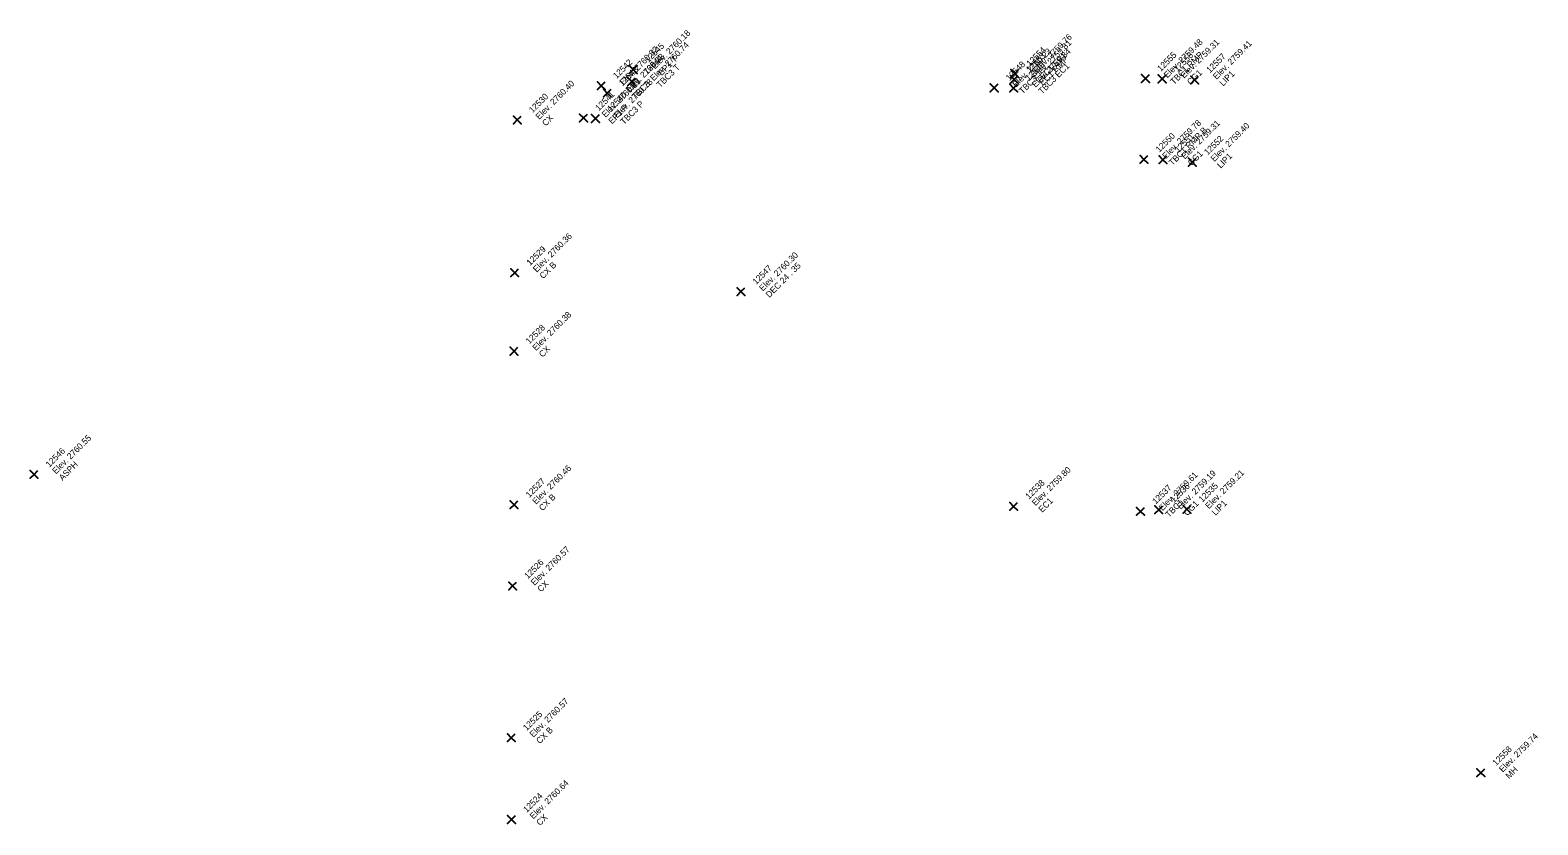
# Model space of a CAD drawing. Extents: x 2493999 to 2503109, y 700767 to 706646.
# Drawn here: x 2502207.3 to 2502265.7, y 702426.3 to 702457 of the extents above; entities that cross this region are included whole.
import ezdxf

# ---------------------------------------------------------------- set-up
doc = ezdxf.new("R2010")
doc.units = 0
doc.layers.add('ALG_CL_BLUE_Horiz', color=7, linetype='Continuous')
doc.layers.add('DES_SURFACE_Existing-Ground', color=7, linetype='Continuous')

msp = doc.modelspace()

# ---------------------------------------------------------------- linework, layer by layer
at = {"layer": 'ALG_CL_BLUE_Horiz'}
for points in [[(2502230.665, 702455.483), (2502230.515, 702455.633), (2502230.665, 702455.483), (2502230.515, 702455.333), (2502230.665, 702455.483), (2502230.815, 702455.333), (2502230.665, 702455.483), (2502230.815, 702455.633)], [(2502229.432, 702454.854), (2502229.282, 702455.004), (2502229.432, 702454.854), (2502229.282, 702454.704), (2502229.432, 702454.854), (2502229.582, 702454.704), (2502229.432, 702454.854), (2502229.582, 702455.004)], [(2502230.61, 702455.016), (2502230.46, 702455.166), (2502230.61, 702455.016), (2502230.46, 702454.866), (2502230.61, 702455.016), (2502230.76, 702454.866), (2502230.61, 702455.016), (2502230.76, 702455.166)], [(2502245.416, 702455.103), (2502245.266, 702455.253), (2502245.416, 702455.103), (2502245.266, 702454.953), (2502245.416, 702455.103), (2502245.566, 702454.953), (2502245.416, 702455.103), (2502245.566, 702455.253)], [(2502245.43, 702455.328), (2502245.28, 702455.478), (2502245.43, 702455.328), (2502245.28, 702455.178), (2502245.43, 702455.328), (2502245.58, 702455.178), (2502245.43, 702455.328), (2502245.58, 702455.478)], [(2502250.493, 702455.137), (2502250.343, 702455.287), (2502250.493, 702455.137), (2502250.343, 702454.987), (2502250.493, 702455.137), (2502250.643, 702454.987), (2502250.493, 702455.137), (2502250.643, 702455.287)], [(2502251.139, 702455.124), (2502250.989, 702455.274), (2502251.139, 702455.124), (2502250.989, 702454.974), (2502251.139, 702455.124), (2502251.289, 702454.974), (2502251.139, 702455.124), (2502251.289, 702455.274)], [(2502252.393, 702455.078), (2502252.243, 702455.228), (2502252.393, 702455.078), (2502252.243, 702454.928), (2502252.393, 702455.078), (2502252.543, 702454.928), (2502252.393, 702455.078), (2502252.543, 702455.228)], [(2502229.662, 702454.571), (2502229.512, 702454.721), (2502229.662, 702454.571), (2502229.512, 702454.421), (2502229.662, 702454.571), (2502229.812, 702454.421), (2502229.662, 702454.571), (2502229.812, 702454.721)], [(2502244.636, 702454.775), (2502244.486, 702454.925), (2502244.636, 702454.775), (2502244.486, 702454.625), (2502244.636, 702454.775), (2502244.786, 702454.625), (2502244.636, 702454.775), (2502244.786, 702454.925)], [(2502245.387, 702454.766), (2502245.237, 702454.916), (2502245.387, 702454.766), (2502245.237, 702454.616), (2502245.387, 702454.766), (2502245.537, 702454.616), (2502245.387, 702454.766), (2502245.537, 702454.916)], [(2502226.178, 702453.53), (2502226.028, 702453.68), (2502226.178, 702453.53), (2502226.028, 702453.38), (2502226.178, 702453.53), (2502226.328, 702453.38), (2502226.178, 702453.53), (2502226.328, 702453.68)], [(2502228.744, 702453.609), (2502228.594, 702453.759), (2502228.744, 702453.609), (2502228.594, 702453.459), (2502228.744, 702453.609), (2502228.894, 702453.459), (2502228.744, 702453.609), (2502228.894, 702453.759)], [(2502229.207, 702453.588), (2502229.057, 702453.738), (2502229.207, 702453.588), (2502229.057, 702453.438), (2502229.207, 702453.588), (2502229.357, 702453.438), (2502229.207, 702453.588), (2502229.357, 702453.738)], [(2502250.434, 702452.005), (2502250.284, 702452.155), (2502250.434, 702452.005), (2502250.284, 702451.855), (2502250.434, 702452.005), (2502250.584, 702451.855), (2502250.434, 702452.005), (2502250.584, 702452.155)], [(2502251.166, 702451.992), (2502251.016, 702452.142), (2502251.166, 702451.992), (2502251.016, 702451.842), (2502251.166, 702451.992), (2502251.316, 702451.842), (2502251.166, 702451.992), (2502251.316, 702452.142)], [(2502252.305, 702451.897), (2502252.155, 702452.047), (2502252.305, 702451.897), (2502252.155, 702451.747), (2502252.305, 702451.897), (2502252.455, 702451.747), (2502252.305, 702451.897), (2502252.455, 702452.047)], [(2502226.082, 702447.623), (2502225.932, 702447.773), (2502226.082, 702447.623), (2502225.932, 702447.473), (2502226.082, 702447.623), (2502226.232, 702447.473), (2502226.082, 702447.623), (2502226.232, 702447.773)], [(2502234.834, 702446.889), (2502234.684, 702447.039), (2502234.834, 702446.889), (2502234.684, 702446.739), (2502234.834, 702446.889), (2502234.984, 702446.739), (2502234.834, 702446.889), (2502234.984, 702447.039)], [(2502226.056, 702444.587), (2502225.906, 702444.737), (2502226.056, 702444.587), (2502225.906, 702444.437), (2502226.056, 702444.587), (2502226.206, 702444.437), (2502226.056, 702444.587), (2502226.206, 702444.737)], [(2502207.478, 702439.816), (2502207.328, 702439.966), (2502207.478, 702439.816), (2502207.328, 702439.666), (2502207.478, 702439.816), (2502207.628, 702439.666), (2502207.478, 702439.816), (2502207.628, 702439.966)], [(2502226.056, 702438.643), (2502225.906, 702438.793), (2502226.056, 702438.643), (2502225.906, 702438.493), (2502226.056, 702438.643), (2502226.206, 702438.493), (2502226.056, 702438.643), (2502226.206, 702438.793)], [(2502245.389, 702438.582), (2502245.239, 702438.732), (2502245.389, 702438.582), (2502245.239, 702438.432), (2502245.389, 702438.582), (2502245.539, 702438.432), (2502245.389, 702438.582), (2502245.539, 702438.732)], [(2502250.299, 702438.388), (2502250.149, 702438.538), (2502250.299, 702438.388), (2502250.149, 702438.238), (2502250.299, 702438.388), (2502250.449, 702438.238), (2502250.299, 702438.388), (2502250.449, 702438.538)], [(2502251.004, 702438.451), (2502250.854, 702438.601), (2502251.004, 702438.451), (2502250.854, 702438.301), (2502251.004, 702438.451), (2502251.154, 702438.301), (2502251.004, 702438.451), (2502251.154, 702438.601)], [(2502252.097, 702438.467), (2502251.947, 702438.617), (2502252.097, 702438.467), (2502251.947, 702438.317), (2502252.097, 702438.467), (2502252.247, 702438.317), (2502252.097, 702438.467), (2502252.247, 702438.617)], [(2502225.997, 702435.502), (2502225.847, 702435.652), (2502225.997, 702435.502), (2502225.847, 702435.352), (2502225.997, 702435.502), (2502226.147, 702435.352), (2502225.997, 702435.502), (2502226.147, 702435.652)], [(2502225.95, 702429.629), (2502225.8, 702429.779), (2502225.95, 702429.629), (2502225.8, 702429.479), (2502225.95, 702429.629), (2502226.1, 702429.479), (2502225.95, 702429.629), (2502226.1, 702429.779)], [(2502263.469, 702428.275), (2502263.319, 702428.425), (2502263.469, 702428.275), (2502263.319, 702428.125), (2502263.469, 702428.275), (2502263.619, 702428.125), (2502263.469, 702428.275), (2502263.619, 702428.425)], [(2502225.956, 702426.465), (2502225.806, 702426.615), (2502225.956, 702426.465), (2502225.806, 702426.315), (2502225.956, 702426.465), (2502226.106, 702426.315), (2502225.956, 702426.465), (2502226.106, 702426.615)]]:
    msp.add_lwpolyline(points, dxfattribs=at)

# ---------------------------------------------------------------- texts
at = {"layer": 'DES_SURFACE_Existing-Ground'}
for s, p in [('Elev. 2760.18', (2502231.514, 702455.483)), ('Elev. 2759.76', (2502246.279, 702455.328)), ('Elev. 2760.32', (2502230.281, 702454.854)), ('12545', (2502231.259, 702455.738)), ('Elev. 2760.74', (2502231.459, 702455.016)), ('Elev. 2760.23', (2502245.485, 702454.775)), ('12554', (2502246.024, 702455.583)), ('Elev. 2759.84', (2502246.236, 702454.766)), ('Elev. 2759.81', (2502246.265, 702455.103)), ('12555', (2502251.087, 702455.392)), ('Elev. 2759.48', (2502251.342, 702455.137)), ('TBC1 RMP', (2502251.596, 702454.882)), ('12556', (2502251.733, 702455.379)), ('Elev. 2759.31', (2502251.988, 702455.124)), ('Elev. 2759.41', (2502253.242, 702455.078)), ('12542', (2502230.026, 702455.109)), ('12543', (2502230.256, 702454.826)), ('Elev. 2760.73', (2502230.511, 702454.571)), ('12544', (2502231.204, 702455.271)), ('TBC3 T', (2502231.713, 702454.761)), ('EP1 T', (2502231.768, 702455.228)), ('12548', (2502245.23, 702455.03)), ('12549', (2502245.981, 702455.021)), ('12553', (2502246.01, 702455.358)), ('TBC3 EC1', (2502246.49, 702454.511)), ('EC1 RMP', (2502246.519, 702454.848)), ('EC1 EP1', (2502246.533, 702455.073)), ('12557', (2502252.987, 702455.333)), ('Elev. 2760.40', (2502227.027, 702453.53)), ('Elev. 2760.25', (2502229.593, 702453.609)), ('Elev. 2760.78', (2502230.056, 702453.588)), ('EP1', (2502230.535, 702454.599)), ('TBC3', (2502230.765, 702454.316)), ('TBC3', (2502245.739, 702454.52)), ('CG1', (2502252.242, 702454.869)), ('LIP1', (2502253.496, 702454.823)), ('12530', (2502226.772, 702453.785)), ('12541', (2502229.338, 702453.864)), ('12540', (2502229.801, 702453.843)), ('EP1 P', (2502229.847, 702453.354)), ('TBC3 P', (2502230.31, 702453.333)), ('CX', (2502227.281, 702453.275)), ('Elev. 2759.78', (2502251.283, 702452.005)), ('TBC1 RMP B', (2502251.537, 702451.75)), ('Elev. 2759.31', (2502252.015, 702451.992)), ('Elev. 2759.40', (2502253.154, 702451.897)), ('12550', (2502251.028, 702452.26)), ('12551', (2502251.76, 702452.247)), ('12552', (2502252.899, 702452.152)), ('CG1', (2502252.269, 702451.737)), ('LIP1', (2502253.408, 702451.642)), ('Elev. 2760.36', (2502226.931, 702447.623)), ('12529', (2502226.676, 702447.878)), ('CX B', (2502227.185, 702447.368)), ('Elev. 2760.30', (2502235.683, 702446.889)), ('DEC 24 . 35', (2502235.937, 702446.634)), ('12547', (2502235.428, 702447.144)), ('Elev. 2760.38', (2502226.905, 702444.587)), ('12528', (2502226.65, 702444.842)), ('CX', (2502227.159, 702444.332)), ('Elev. 2760.55', (2502208.327, 702439.816)), ('12546', (2502208.072, 702440.071)), ('ASPH', (2502208.581, 702439.561)), ('Elev. 2760.46', (2502226.905, 702438.643)), ('Elev. 2759.80', (2502246.238, 702438.582)), ('Elev. 2759.61', (2502251.148, 702438.388)), ('Elev. 2759.19', (2502251.853, 702438.451)), ('Elev. 2759.21', (2502252.946, 702438.467)), ('12527', (2502226.65, 702438.898)), ('12538', (2502245.983, 702438.837)), ('12537', (2502250.893, 702438.643)), ('12536', (2502251.598, 702438.706)), ('12535', (2502252.691, 702438.722)), ('CX B', (2502227.159, 702438.388)), ('EC1', (2502246.492, 702438.327)), ('TBC1', (2502251.402, 702438.133)), ('CG1', (2502252.107, 702438.196)), ('LIP1', (2502253.2, 702438.212)), ('Elev. 2760.57', (2502226.846, 702435.502)), ('12526', (2502226.591, 702435.757)), ('CX', (2502227.1, 702435.247)), ('Elev. 2760.57', (2502226.799, 702429.629)), ('12525', (2502226.544, 702429.884)), ('CX B', (2502227.053, 702429.374)), ('Elev. 2759.74', (2502264.318, 702428.275)), ('12558', (2502264.063, 702428.53)), ('MH', (2502264.572, 702428.02)), ('Elev. 2760.64', (2502226.805, 702426.465)), ('12524', (2502226.55, 702426.72)), ('CX', (2502227.059, 702426.21))]:
    msp.add_text(s, height=0.24, rotation=45, dxfattribs=at).set_placement(p)

doc.saveas('drawing.dxf')
